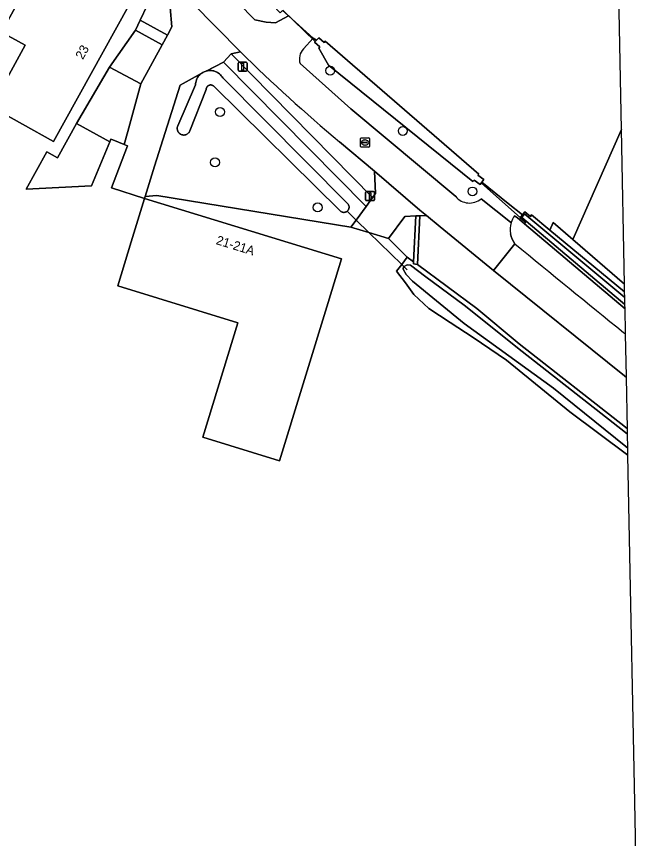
# Model space of a CAD drawing. Extents: x 163859 to 164644, y 379566 to 382155.
# Drawn here: x 164538.8 to 164607.1, y 381497.9 to 381588.1 of the extents above; entities that cross this region are included whole.
import ezdxf

# ---------------------------------------------------------------- set-up
doc = ezdxf.new("R2010")
doc.units = 0
for name, color, linetype in [('IMGEO_Berm_groen', 7, 'Continuous'), ('IMGEO_Boom', 7, 'Continuous'), ('IMGEO_Duiker', 7, 'Continuous'), ('IMGEO_Erf', 7, 'Continuous'), ('IMGEO_Fietspad_gesloten', 7, 'Continuous'), ('IMGEO_Fietspad_open', 7, 'Continuous'), ('IMGEO_Grasland_agrarisch', 7, 'Continuous'), ('IMGEO_Grasland_overig', 7, 'Continuous'), ('IMGEO_Groenvoorziening', 7, 'Continuous'), ('IMGEO_Lichtmast', 7, 'Continuous'), ('IMGEO_Oever', 7, 'Continuous'), ('IMGEO_Pand', 7, 'Continuous'), ('IMGEO_Pand_nummerreeks', 7, 'Continuous'), ('IMGEO_Rijbaan_lokaal_gesloten', 7, 'Continuous'), ('IMGEO_Rioolput', 7, 'Continuous'), ('IMGEO_Sloot', 7, 'Continuous'), ('IMGEO_Voetpad_open', 7, 'Continuous'), ('IMGEO_Waterloop', 7, 'Continuous')]:
    doc.layers.add(name, color=color, linetype=linetype)

msp = doc.modelspace()

# ---------------------------------------------------------------- linework, layer by layer
at = {"layer": 'IMGEO_Berm_groen'}
for points in [[(164605.822, 381548.486), (164605.611, 381548.656), (164591.227, 381560.246), (164585.368, 381565.034), (164583.861, 381566.281), (164583.116, 381566.249), (164582.857, 381560.895), (164589.379, 381556.063), (164594.045, 381552.165), (164605.72, 381543.019), (164605.934, 381542.848), (164605.934, 381542.852), (164605.822, 381548.486)], [(164605.727, 381553.258), (164605.725, 381553.376), (164605.673, 381556.023), (164594.64, 381565.355), (164593.85, 381566), (164593.54, 381566.251)], [(164593.08, 381564.265), (164593.153, 381563.97), (164593.262, 381563.685), (164593.406, 381563.417), (164593.581, 381563.168)]]:
    msp.add_lwpolyline(points, dxfattribs=at)
for centre, radius, start, end in [((164595.647, 381564.719), 2.605, 143.9872, 162.70119), ((164595.67, 381564.713), 2.629, 162.72918, 189.82216), ((165748.835, 382966.677), 1817.815, 230.54157, 231.027189), ((165756.783, 382976.73), 1830.629, 231.031703, 231.04013)]:
    msp.add_arc(centre, radius, start, end, dxfattribs=at)
at = {"layer": 'IMGEO_Boom'}
for centre in [(164573.282, 381582.182), (164561.176, 381577.645), (164581.257, 381575.562), (164560.627, 381572.111), (164588.912, 381568.913), (164571.907, 381567.161)]:
    msp.add_circle(centre, 0.489, dxfattribs=at)
at = {"layer": 'IMGEO_Duiker'}
for points in [[(164571.59, 381585.436), (164568.072, 381588.807)], [(164594.155, 381566.041), (164589.894, 381569.832)], [(164575.135, 381566.735), (164576.129, 381565.77), (164577.537, 381564.402), (164581.136, 381560.907), (164581.748, 381560.312)]]:
    msp.add_lwpolyline(points, dxfattribs=at)
at = {"layer": 'IMGEO_Erf'}
for points in [[(164568.683, 381588.204), (164571.405, 381585.74), (164571.774, 381585.529), (164572.012, 381585.778), (164572.6, 381585.277), (164572.738, 381585.416), (164589.619, 381570.826), (164589.499, 381570.686), (164590.176, 381570.21), (164589.951, 381569.924), (164592.85, 381567.588), (164594.399, 381566.34), (164594.666, 381566.669), (164595.277, 381566.177), (164595.403, 381566.341), (164597.416, 381564.68), (164597.787, 381565.492), (164599.928, 381563.653), (164605.281, 381575.702), (164604.653, 381607.333)], [(164552.483, 381591.733), (164542.859, 381574.412), (164536.015, 381578.215), (164539.764, 381584.963), (164537.142, 381586.42), (164539.57, 381590.791)], [(164552.886, 381568.155), (164549.259, 381569.312), (164551.011, 381573.919), (164550.634, 381574.072), (164549.376, 381574.581), (164549.18, 381574.66), (164549.064, 381574.346), (164547.042, 381569.534), (164539.879, 381569.16), (164542.159, 381573.27), (164543.33, 381572.62), (164545.414, 381576.377), (164549.024, 381582.566), (164551.898, 381586.619), (164552.413, 381587.729), (164553.919, 381590.974)], [(164607.054, 381486.095), (164606.786, 381500), (164606.102, 381534.42), (164605.992, 381539.946), (164599.611, 381544.711), (164592.647, 381550.404), (164589.006, 381552.86), (164586.466, 381554.511), (164584.117, 381556.077), (164582.487, 381557.58), (164581.535, 381558.871), (164580.561, 381560.156), (164581.136, 381560.907), (164577.537, 381564.402), (164575.561, 381565.01), (164554.235, 381568.477), (164552.951, 381568.366), (164552.886, 381568.155)]]:
    msp.add_lwpolyline(points, dxfattribs=at)
for points in [[(164552.886, 381568.155), (164574.506, 381561.505), (164573.039, 381556.726), (164567.703, 381539.342), (164559.271, 381541.93), (164563.129, 381554.5), (164549.934, 381558.559), (164551.416, 381563.377)], [(164579.682, 381563.742), (164577.537, 381564.402), (164581.136, 381560.907), (164581.753, 381561.713)]]:
    msp.add_lwpolyline(points, close=True, dxfattribs=at)
at = {"layer": 'IMGEO_Fietspad_gesloten'}
for points in [[(164593.581, 381563.168), (164591.227, 381560.246), (164605.611, 381548.656), (164605.822, 381548.486)], [(164605.822, 381548.486), (164605.82, 381548.593), (164605.727, 381553.258)]]:
    msp.add_lwpolyline(points, dxfattribs=at)
for centre, radius, start, end in [((165748.835, 382966.677), 1817.815, 230.54157, 231.027189), ((165756.783, 382976.73), 1830.629, 231.031703, 231.04013)]:
    msp.add_arc(centre, radius, start, end, dxfattribs=at)
at = {"layer": 'IMGEO_Fietspad_open'}
msp.add_lwpolyline([(164562.396, 381584.01), (164561.548, 381583.102), (164577.234, 381567.247), (164577.938, 381568.255)], close=True, dxfattribs=at)
at = {"layer": 'IMGEO_Grasland_agrarisch'}
msp.add_lwpolyline([(164605.618, 381558.732), (164605.281, 381575.702), (164599.928, 381563.653)], close=True, dxfattribs=at)
at = {"layer": 'IMGEO_Grasland_overig'}
msp.add_lwpolyline([(164583.116, 381566.249), (164582.677, 381566.231), (164582.446, 381561.199), (164582.435, 381560.951), (164582.857, 381560.895)], close=True, dxfattribs=at)
msp.add_lwpolyline([(164605.635, 381557.901), (164605.618, 381558.732), (164599.928, 381563.653), (164597.787, 381565.492), (164597.416, 381564.68), (164605.635, 381557.901)], dxfattribs=at)
at = {"layer": 'IMGEO_Groenvoorziening'}
for points in [[(164529.998, 381629.477), (164529.062, 381628.074), (164528.858, 381625.543), (164529.296, 381624.655), (164543.311, 381609.901), (164564.981, 381587.752), (164566.26, 381587.51), (164567.284, 381587.443), (164568.683, 381588.204), (164568.04, 381588.776), (164567.797, 381588.537), (164566.969, 381589.374), (164566.798, 381589.232), (164530.344, 381625.941), (164529.918, 381627.464), (164530.675, 381628.727)], [(164553.919, 381590.974), (164552.413, 381587.729), (164555.392, 381586.084), (164555.888, 381586.983), (164555.704, 381589.13)], [(164554.802, 381585.016), (164551.898, 381586.619), (164549.024, 381582.566), (164552.463, 381580.716)], [(164560.518, 381580.44), (164560.489, 381580.471), (164560.458, 381580.499), (164560.424, 381580.525), (164560.388, 381580.547), (164560.351, 381580.567), (164560.311, 381580.582), (164560.271, 381580.595), (164560.23, 381580.604), (164560.188, 381580.609), (164560.145, 381580.611), (164560.103, 381580.609), (164560.061, 381580.603), (164560.02, 381580.594), (164559.98, 381580.581), (164559.941, 381580.565), (164559.903, 381580.545), (164559.868, 381580.522), (164559.834, 381580.496), (164559.803, 381580.468), (164559.775, 381580.437), (164559.749, 381580.403), (164559.726, 381580.367), (164559.707, 381580.33), (164559.69, 381580.291), (164559.678, 381580.25), (164559.668, 381580.209), (164559.663, 381580.167), (164559.661, 381580.125), (164557.857, 381575.568), (164557.832, 381575.51), (164557.801, 381575.454), (164557.766, 381575.402), (164557.726, 381575.352), (164557.682, 381575.307), (164557.634, 381575.265), (164557.583, 381575.228), (164557.528, 381575.195), (164557.471, 381575.168), (164557.412, 381575.145), (164557.351, 381575.128), (164557.288, 381575.116), (164557.225, 381575.11), (164557.162, 381575.11), (164557.099, 381575.115), (164557.036, 381575.125), (164556.975, 381575.142), (164556.915, 381575.163), (164556.857, 381575.19), (164556.802, 381575.221), (164556.75, 381575.258), (164556.702, 381575.298), (164556.657, 381575.343), (164556.616, 381575.392), (164556.58, 381575.444), (164556.549, 381575.499), (164556.522, 381575.557), (164556.501, 381575.617), (164556.485, 381575.678), (164556.475, 381575.741), (164556.47, 381575.804), (164556.471, 381575.867), (164556.477, 381575.93), (164556.489, 381575.993), (164556.506, 381576.054), (164556.529, 381576.113), (164558.481, 381580.62), (164558.489, 381580.759), (164558.51, 381580.896), (164558.542, 381581.031), (164558.585, 381581.163), (164558.64, 381581.29), (164558.706, 381581.412), (164558.782, 381581.528), (164558.867, 381581.638), (164558.962, 381581.739), (164559.066, 381581.832), (164559.098, 381581.856), (164556.81, 381580.576), (164553.97, 381571.678), (164552.951, 381568.366), (164554.235, 381568.477), (164575.561, 381565.01), (164576.129, 381565.77), (164577.234, 381567.247), (164561.548, 381583.102), (164559.646, 381582.135), (164559.679, 381582.145), (164559.814, 381582.174), (164559.952, 381582.192), (164560.091, 381582.197), (164560.229, 381582.191), (164560.367, 381582.172), (164560.502, 381582.142), (164560.635, 381582.1), (164560.763, 381582.047), (164560.886, 381581.983), (164561.003, 381581.908), (164561.113, 381581.824), (164561.216, 381581.73), (164561.31, 381581.628), (164561.395, 381581.519), (164561.47, 381581.402), (164575.192, 381567.583), (164575.226, 381567.545), (164575.256, 381567.505), (164575.283, 381567.462), (164575.305, 381567.417), (164575.324, 381567.37), (164575.338, 381567.322), (164575.348, 381567.272), (164575.354, 381567.222), (164575.355, 381567.171), (164575.352, 381567.121), (164575.344, 381567.071), (164575.332, 381567.022), (164575.315, 381566.974), (164575.294, 381566.928), (164575.27, 381566.884), (164575.241, 381566.843), (164575.209, 381566.804), (164575.174, 381566.768), (164575.135, 381566.735), (164575.095, 381566.707), (164575.053, 381566.682), (164575.009, 381566.661), (164574.964, 381566.644), (164574.917, 381566.631), (164574.869, 381566.622), (164574.821, 381566.617), (164574.772, 381566.616), (164574.724, 381566.619), (164574.675, 381566.627), (164574.628, 381566.639), (164574.582, 381566.654), (164574.538, 381566.674), (164574.495, 381566.697), (164574.454, 381566.724), (164574.416, 381566.754)], [(164582.446, 381561.199), (164582.677, 381566.231), (164581.474, 381566.18), (164579.682, 381563.742), (164581.753, 381561.713)]]:
    msp.add_lwpolyline(points, close=True, dxfattribs=at)
for points in [[(164589.951, 381569.924), (164589.761, 381569.682), (164589.081, 381570.155), (164588.959, 381570.001), (164573.092, 381582.772), (164572.027, 381584.642), (164572.135, 381584.791), (164571.564, 381585.309), (164571.774, 381585.529), (164571.405, 381585.74), (164570.328, 381584.58)], [(164563.421, 381584.231), (164562.396, 381584.01), (164577.938, 381568.255), (164578.249, 381568.674), (164578.135, 381571.127), (164574.289, 381574.373)], [(164569.963, 381582.948), (164575.559, 381577.97), (164587.08, 381568.347)], [(164593.54, 381566.251), (164593.85, 381566), (164594.64, 381565.355), (164594.764, 381565.491), (164594.138, 381566.02), (164594.399, 381566.34), (164592.85, 381567.588), (164589.951, 381569.924)], [(164589.861, 381568.105), (164593.091, 381565.548), (164593.16, 381565.494)]]:
    msp.add_lwpolyline(points, dxfattribs=at)
for centre, radius, start, end in [((164697.785, 381721.441), 192.042, 225.60052, 229.97924), ((164571.583, 381583.443), 1.694, 137.81133, 196.97498), ((164588.591, 381569.616), 1.974, 220.02188, 310.03153), ((164595.647, 381564.719), 2.605, 143.9872, 162.70119)]:
    msp.add_arc(centre, radius, start, end, dxfattribs=at)
at = {"layer": 'IMGEO_Lichtmast'}
for p, q in [((164563.165, 381582.215), (164563.165, 381583.015)), ((164563.165, 381583.015), (164563.165, 381582.215)), ((164563.265, 381583.115), (164564.055, 381583.115)), ((164564.055, 381583.115), (164563.265, 381583.115)), ((164564.155, 381583.015), (164564.155, 381582.215)), ((164564.155, 381582.215), (164564.155, 381583.015)), ((164564.055, 381582.115), (164563.265, 381582.115)), ((164563.265, 381582.115), (164564.055, 381582.115)), ((164577.164, 381568.004), (164577.164, 381568.804)), ((164577.164, 381568.804), (164577.164, 381568.004)), ((164577.264, 381568.904), (164578.054, 381568.904)), ((164578.054, 381568.904), (164577.264, 381568.904)), ((164578.154, 381568.804), (164578.154, 381568.004)), ((164578.154, 381568.004), (164578.154, 381568.804)), ((164578.054, 381567.904), (164577.264, 381567.904)), ((164577.264, 381567.904), (164578.054, 381567.904))]:
    msp.add_line(p, q, dxfattribs=at)
for points in [[(164563.585, 381582.99), (164563.735, 381582.99), (164563.735, 381582.24), (164563.585, 381582.24), (164563.585, 381582.99)], [(164577.584, 381568.779), (164577.734, 381568.779), (164577.734, 381568.029), (164577.584, 381568.029), (164577.584, 381568.779)]]:
    msp.add_lwpolyline(points, dxfattribs=at)
for centre, start, end in [((164563.265, 381583.015), 90, 180), ((164563.265, 381583.015), 90, 180), ((164564.055, 381583.015), 0, 90), ((164564.055, 381583.015), 360, 90), ((164563.265, 381582.215), 180, 270), ((164563.265, 381582.215), 180, 270), ((164564.055, 381582.215), 270, 0), ((164564.055, 381582.215), 270, 0), ((164577.264, 381568.804), 90, 180), ((164577.264, 381568.804), 90, 180), ((164578.054, 381568.804), 0, 90), ((164578.054, 381568.804), 360, 90), ((164577.264, 381568.004), 180, 270), ((164577.264, 381568.004), 180, 270), ((164578.054, 381568.004), 270, 0), ((164578.054, 381568.004), 270, 0)]:
    msp.add_arc(centre, 0.1, start, end, dxfattribs=at)
at = {"layer": 'IMGEO_Oever'}
for points in [[(164605.635, 381557.901), (164597.416, 381564.68), (164595.403, 381566.341), (164595.277, 381566.177), (164594.666, 381566.669), (164594.399, 381566.34), (164594.138, 381566.02), (164594.764, 381565.491), (164594.64, 381565.355), (164605.673, 381556.023), (164605.673, 381556.024), (164605.663, 381556.505), (164594.327, 381566.039), (164594.665, 381566.429), (164605.648, 381557.257), (164605.635, 381557.901)], [(164605.934, 381542.848), (164605.72, 381543.019), (164594.045, 381552.165), (164589.379, 381556.063), (164582.857, 381560.895), (164582.435, 381560.951), (164582.446, 381561.199), (164581.753, 381561.713), (164581.136, 381560.907), (164580.561, 381560.156), (164581.535, 381558.871), (164582.487, 381557.58), (164584.117, 381556.077), (164586.466, 381554.511), (164589.006, 381552.86), (164592.647, 381550.404), (164599.611, 381544.711), (164605.992, 381539.946), (164605.98, 381540.562), (164605.976, 381540.74), (164605.761, 381540.909), (164597.818, 381547.311), (164588.012, 381554.426), (164582.318, 381559.062), (164581.619, 381559.802), (164581.281, 381560.374), (164581.351, 381560.651), (164581.725, 381560.861), (164582.085, 381560.818), (164583.799, 381559.548), (164588.012, 381556.437), (164594.365, 381551.343), (164605.732, 381542.438), (164605.946, 381542.268)]]:
    msp.add_lwpolyline(points, close=True, dxfattribs=at)
at = {"layer": 'IMGEO_Pand'}
for points in [[(164552.483, 381591.733), (164548.03, 381594.24), (164545.684, 381595.561), (164542.21, 381589.324), (164539.57, 381590.791), (164537.142, 381586.42), (164539.764, 381584.963), (164536.015, 381578.215), (164542.859, 381574.412)], [(164539.879, 381569.16), (164547.042, 381569.534), (164549.064, 381574.346), (164545.414, 381576.377), (164543.33, 381572.62), (164542.159, 381573.27)], [(164573.039, 381556.726), (164574.506, 381561.505), (164552.886, 381568.155), (164551.416, 381563.377), (164549.934, 381558.559), (164563.129, 381554.5), (164559.271, 381541.93), (164567.703, 381539.342)]]:
    msp.add_lwpolyline(points, close=True, dxfattribs=at)
at = {"layer": 'IMGEO_Rijbaan_lokaal_gesloten'}
for points in [[(164517.634, 381632.432), (164526.997, 381621.944), (164529.934, 381618.654), (164540.553, 381607.686), (164552.405, 381595.537), (164555.453, 381592.376), (164563.421, 381584.231)], [(164570.328, 381584.58), (164571.405, 381585.74), (164568.683, 381588.204), (164567.284, 381587.443), (164566.26, 381587.51), (164564.981, 381587.752), (164543.311, 381609.901)], [(164587.08, 381568.347), (164575.559, 381577.97), (164569.963, 381582.948)], [(164574.289, 381574.373), (164578.135, 381571.127), (164583.144, 381566.874), (164583.861, 381566.281), (164585.368, 381565.034), (164591.227, 381560.246), (164593.581, 381563.168), (164593.406, 381563.417), (164593.262, 381563.685), (164593.153, 381563.97), (164593.08, 381564.265)], [(164593.16, 381565.494), (164593.091, 381565.548), (164589.861, 381568.105)]]:
    msp.add_lwpolyline(points, dxfattribs=at)
for centre, radius, start, end in [((164697.785, 381721.441), 192.042, 225.60052, 229.97924), ((164571.583, 381583.443), 1.694, 137.81133, 196.97498), ((164588.591, 381569.616), 1.974, 220.02188, 310.03153), ((164595.67, 381564.713), 2.629, 162.72918, 189.82216)]:
    msp.add_arc(centre, radius, start, end, dxfattribs=at)
at = {"layer": 'IMGEO_Rioolput'}
for p, q in [((164576.608, 381573.86), (164576.608, 381574.712)), ((164576.683, 381574.786), (164577.535, 381574.786)), ((164576.867, 381574.28), (164576.867, 381574.292)), ((164577.305, 381574.243), (164576.907, 381574.243)), ((164576.91, 381574.329), (164577.308, 381574.329)), ((164577.096, 381574.566), (164577.121, 381574.566)), ((164577.351, 381574.292), (164577.351, 381574.28)), ((164577.609, 381574.712), (164577.609, 381573.86)), ((164577.535, 381573.786), (164576.683, 381573.786)), ((164577.119, 381574.006), (164577.094, 381574.006))]:
    msp.add_line(p, q, dxfattribs=at)
for points in [[(164576.608, 381573.86), (164576.608, 381574.712)], [(164576.683, 381574.786), (164577.535, 381574.786)], [(164577.609, 381574.712), (164577.609, 381573.86)], [(164577.535, 381573.786), (164576.683, 381573.786)]]:
    msp.add_lwpolyline(points, dxfattribs=at)
for centre, radius, start, end in [((164576.685, 381574.71), 0.0765, 91.55205, 178.44795), ((164576.685, 381574.71), 0.0765, 91.55205, 178.44795), ((164576.907, 381574.289), 0.0403, 85.87752, 175.75265), ((164576.904, 381574.279), 0.0366, 178.93798, 274.71019), ((164577.308, 381574.286), 0.043, 264.86636, 352.45326), ((164577.312, 381574.291), 0.0386, 1.73085, 96.63898), ((164577.533, 381574.71), 0.0765, 1.55205, 88.44795), ((164577.533, 381574.71), 0.0765, 1.55205, 88.44795), ((164576.685, 381573.862), 0.0765, 181.55205, 268.44795), ((164576.685, 381573.862), 0.0765, 181.55205, 268.44795), ((164577.533, 381573.862), 0.0765, 271.55205, 358.44795), ((164577.533, 381573.862), 0.0765, 271.55205, 358.44795)]:
    msp.add_arc(centre, radius, start, end, dxfattribs=at)
for centre, major_axis, ratio, start_param, end_param in [((164577.095, 381574.286), (-0.387, 0.002), 0.722429, 4.712389, 7.853982), ((164577.12, 381574.286), (-0.39, 0.002), 0.717154, 1.570796, 4.712389)]:
    msp.add_ellipse(centre, major_axis=major_axis, ratio=ratio, start_param=start_param, end_param=end_param, dxfattribs=at)
at = {"layer": 'IMGEO_Sloot'}
for points in [[(164605.648, 381557.257), (164594.665, 381566.429), (164594.327, 381566.039), (164605.663, 381556.505), (164605.654, 381556.966)], [(164605.976, 381540.74), (164605.946, 381542.268), (164605.732, 381542.438), (164594.365, 381551.343), (164588.012, 381556.437), (164583.799, 381559.548), (164582.085, 381560.818), (164581.725, 381560.861), (164581.351, 381560.651), (164581.281, 381560.374), (164581.619, 381559.802), (164582.318, 381559.062), (164588.012, 381554.426), (164597.818, 381547.311), (164605.761, 381540.909)]]:
    msp.add_lwpolyline(points, close=True, dxfattribs=at)
at = {"layer": 'IMGEO_Voetpad_open'}
for points in [[(164559.098, 381581.856), (164559.176, 381581.915), (164559.294, 381581.989), (164559.418, 381582.052), (164559.546, 381582.104), (164559.646, 381582.135), (164561.548, 381583.102), (164562.396, 381584.01), (164563.421, 381584.231), (164555.453, 381592.376), (164555.475, 381592.172), (164555.704, 381589.13), (164555.888, 381586.983), (164555.392, 381586.084), (164554.802, 381585.016), (164552.463, 381580.716), (164551.028, 381575.502), (164550.634, 381574.072), (164551.011, 381573.919), (164549.259, 381569.312), (164552.886, 381568.155), (164552.951, 381568.366), (164553.97, 381571.678), (164556.81, 381580.576)], [(164552.413, 381587.729), (164551.898, 381586.619), (164554.802, 381585.016), (164555.392, 381586.084)], [(164552.463, 381580.716), (164549.024, 381582.566), (164545.414, 381576.377), (164549.064, 381574.346), (164549.18, 381574.66), (164549.376, 381574.581), (164550.634, 381574.072), (164551.028, 381575.502)], [(164577.234, 381567.247), (164576.129, 381565.77), (164575.561, 381565.01), (164577.537, 381564.402), (164579.682, 381563.742), (164581.474, 381566.18), (164582.677, 381566.231), (164583.116, 381566.249), (164583.861, 381566.281), (164583.144, 381566.874), (164578.135, 381571.127), (164578.249, 381568.674), (164577.938, 381568.255)]]:
    msp.add_lwpolyline(points, close=True, dxfattribs=at)
at = {"layer": 'IMGEO_Waterloop'}
for points in [[(164572.738, 381585.416), (164572.6, 381585.277), (164572.012, 381585.778), (164571.774, 381585.529), (164571.564, 381585.309), (164572.135, 381584.791), (164572.027, 381584.642), (164573.092, 381582.772), (164588.959, 381570.001), (164589.081, 381570.155), (164589.761, 381569.682), (164589.951, 381569.924), (164590.176, 381570.21), (164589.499, 381570.686), (164589.619, 381570.826)], [(164561.47, 381581.402), (164561.395, 381581.519), (164561.31, 381581.628), (164561.216, 381581.73), (164561.113, 381581.824), (164561.003, 381581.908), (164560.886, 381581.983), (164560.763, 381582.047), (164560.635, 381582.1), (164560.502, 381582.142), (164560.367, 381582.172), (164560.229, 381582.191), (164560.091, 381582.197), (164559.952, 381582.192), (164559.814, 381582.174), (164559.679, 381582.145), (164559.646, 381582.135), (164559.546, 381582.104), (164559.418, 381582.052), (164559.294, 381581.989), (164559.176, 381581.915), (164559.098, 381581.856), (164559.066, 381581.832), (164558.962, 381581.739), (164558.867, 381581.638), (164558.782, 381581.528), (164558.706, 381581.412), (164558.64, 381581.29), (164558.585, 381581.163), (164558.542, 381581.031), (164558.51, 381580.896), (164558.489, 381580.759), (164558.481, 381580.62), (164556.529, 381576.113), (164556.506, 381576.054), (164556.489, 381575.993), (164556.477, 381575.93), (164556.471, 381575.867), (164556.47, 381575.804), (164556.475, 381575.741), (164556.485, 381575.678), (164556.501, 381575.617), (164556.522, 381575.557), (164556.549, 381575.499), (164556.58, 381575.444), (164556.616, 381575.392), (164556.657, 381575.343), (164556.702, 381575.298), (164556.75, 381575.258), (164556.802, 381575.221), (164556.857, 381575.19), (164556.915, 381575.163), (164556.975, 381575.142), (164557.036, 381575.125), (164557.099, 381575.115), (164557.162, 381575.11), (164557.225, 381575.11), (164557.288, 381575.116), (164557.351, 381575.128), (164557.412, 381575.145), (164557.471, 381575.168), (164557.528, 381575.195), (164557.583, 381575.228), (164557.634, 381575.265), (164557.682, 381575.307), (164557.726, 381575.352), (164557.766, 381575.402), (164557.801, 381575.454), (164557.832, 381575.51), (164557.857, 381575.568), (164559.661, 381580.125), (164559.663, 381580.167), (164559.668, 381580.209), (164559.678, 381580.25), (164559.69, 381580.291), (164559.707, 381580.33), (164559.726, 381580.367), (164559.749, 381580.403), (164559.775, 381580.437), (164559.803, 381580.468), (164559.834, 381580.496), (164559.868, 381580.522), (164559.903, 381580.545), (164559.941, 381580.565), (164559.98, 381580.581), (164560.02, 381580.594), (164560.061, 381580.603), (164560.103, 381580.609), (164560.145, 381580.611), (164560.188, 381580.609), (164560.23, 381580.604), (164560.271, 381580.595), (164560.311, 381580.582), (164560.351, 381580.567), (164560.388, 381580.547), (164560.424, 381580.525), (164560.458, 381580.499), (164560.489, 381580.471), (164560.518, 381580.44), (164574.416, 381566.754), (164574.454, 381566.724), (164574.495, 381566.697), (164574.538, 381566.674), (164574.582, 381566.654), (164574.628, 381566.639), (164574.675, 381566.627), (164574.724, 381566.619), (164574.772, 381566.616), (164574.821, 381566.617), (164574.869, 381566.622), (164574.917, 381566.631), (164574.964, 381566.644), (164575.009, 381566.661), (164575.053, 381566.682), (164575.095, 381566.707), (164575.135, 381566.735), (164575.174, 381566.768), (164575.209, 381566.804), (164575.241, 381566.843), (164575.27, 381566.884), (164575.294, 381566.928), (164575.315, 381566.974), (164575.332, 381567.022), (164575.344, 381567.071), (164575.352, 381567.121), (164575.355, 381567.171), (164575.354, 381567.222), (164575.348, 381567.272), (164575.338, 381567.322), (164575.324, 381567.37), (164575.305, 381567.417), (164575.283, 381567.462), (164575.256, 381567.505), (164575.226, 381567.545), (164575.192, 381567.583)]]:
    msp.add_lwpolyline(points, close=True, dxfattribs=at)

# ---------------------------------------------------------------- texts
at = {"layer": 'IMGEO_Pand_nummerreeks'}
for s, rotation, p in [('23', 60.74499, (164546.095, 381583.331)), ('21-21A', 342.90294, (164560.668, 381563.146))]:
    msp.add_text(s, height=1, rotation=rotation, dxfattribs=at).set_placement(p)

doc.saveas('drawing.dxf')
